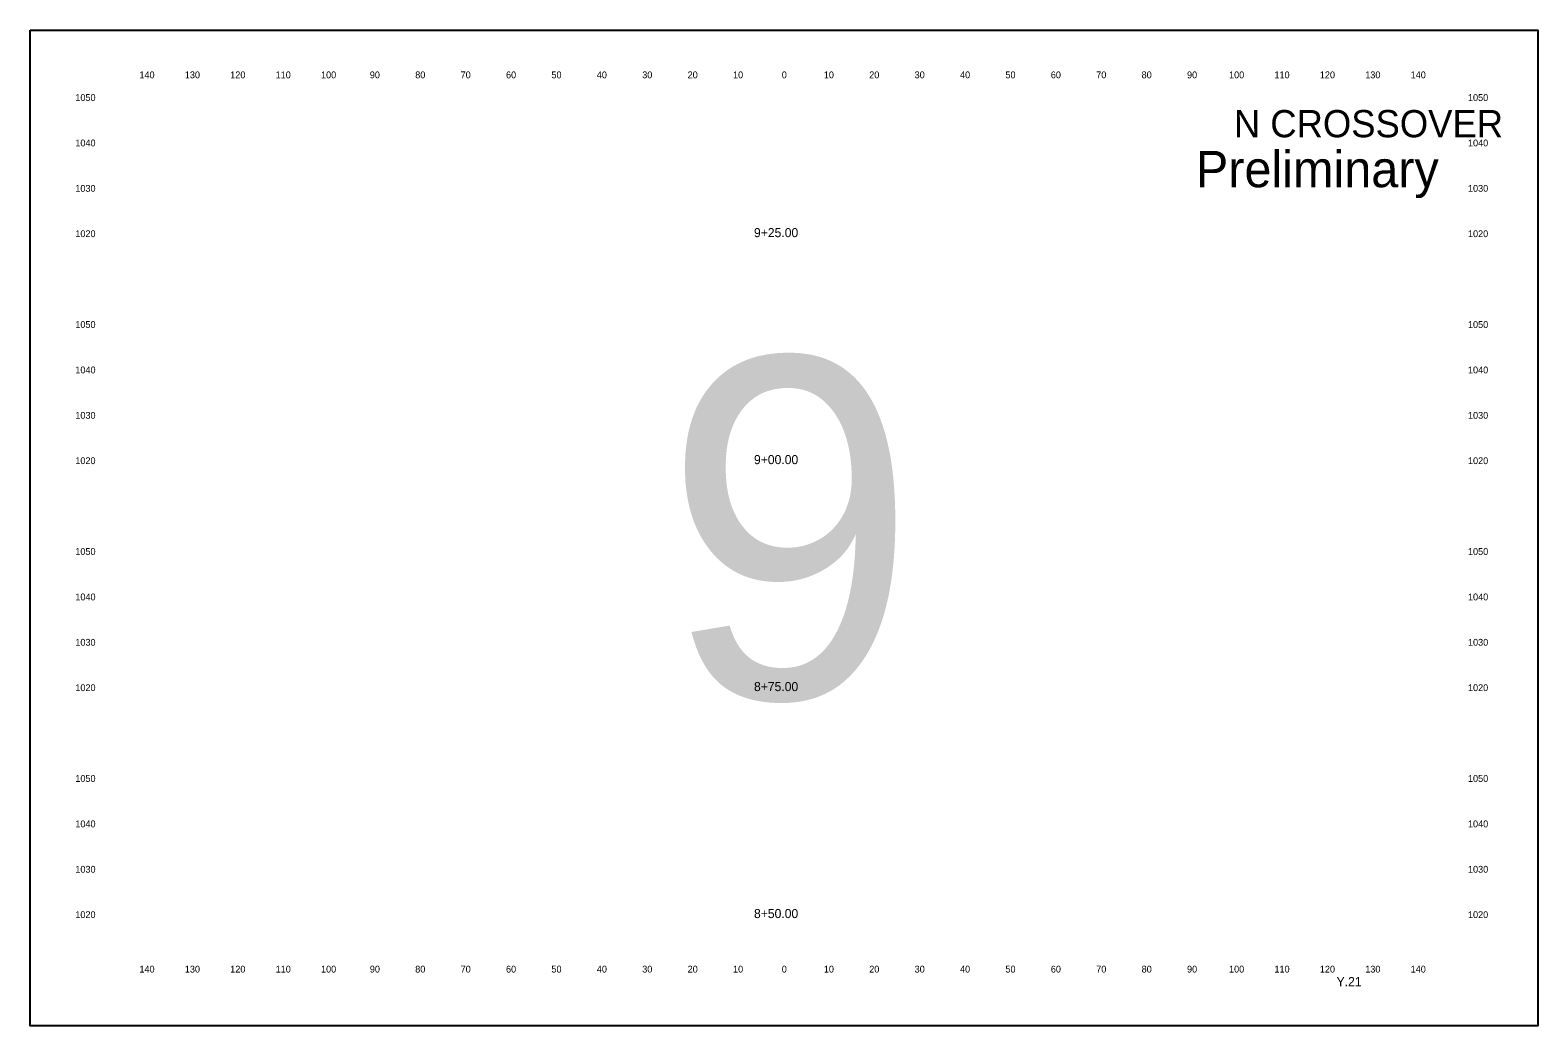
# Model space of a CAD drawing. Extents: x 10123 to 14767, y 9730 to 9950.
# Drawn here: x 13003.2 to 13335.3, y 9730.3 to 9949.6 of the extents above; entities that cross this region are included whole.
import ezdxf

# ---------------------------------------------------------------- set-up
doc = ezdxf.new("R2010")
doc.units = 0
for name, color, linetype in [('dsnTextCpn', 7, 'Continuous'), ('dsnTextCpnTitleSheetLocDesc', 7, 'Continuous'), ('dsnTextCpnTitleSheetPIN', 7, 'Continuous'), ('dsnTextCpnTitleSheetWorkType', 7, 'Continuous')]:
    doc.layers.add(name, color=color, linetype=linetype)

msp = doc.modelspace()

# ---------------------------------------------------------------- linework, layer by layer
at = {"layer": 'dsnTextCpnTitleSheetWorkType'}
msp.add_lwpolyline([(13003.21, 9949.6), (13335.29, 9949.6), (13335.29, 9730.26), (13003.21, 9730.26)], close=True, dxfattribs=at)

# ---------------------------------------------------------------- texts
at = {"layer": 'dsnTextCpn'}
for s, height, p in [('140', 1.5, (13027.27, 9939)), ('130', 1.5, (13037.27, 9939)), ('120', 1.5, (13047.27, 9939)), ('110', 1.5, (13057.27, 9939)), ('100', 1.5, (13067.27, 9939)), ('90', 1.5, (13078.02, 9939)), ('80', 1.5, (13088.02, 9939)), ('70', 1.5, (13098.02, 9939)), ('60', 1.5, (13108.02, 9939)), ('50', 1.5, (13118.02, 9939)), ('40', 1.5, (13128.02, 9939)), ('30', 1.5, (13138.02, 9939)), ('20', 1.5, (13148.02, 9939)), ('10', 1.5, (13158.02, 9939)), ('0', 1.5, (13168.76, 9939)), ('0', 1.5, (13168.76, 9939)), ('10', 1.5, (13178.02, 9939)), ('20', 1.5, (13188.02, 9939)), ('30', 1.5, (13198.02, 9939)), ('40', 1.5, (13208.02, 9939)), ('50', 1.5, (13218.02, 9939)), ('60', 1.5, (13228.02, 9939)), ('70', 1.5, (13238.02, 9939)), ('80', 1.5, (13248.02, 9939)), ('90', 1.5, (13258.02, 9939)), ('100', 1.5, (13267.27, 9939)), ('110', 1.5, (13277.27, 9939)), ('120', 1.5, (13287.27, 9939)), ('130', 1.5, (13297.27, 9939)), ('140', 1.5, (13307.27, 9939)), ('1050', 1.5, (13013.15, 9934)), ('1050', 1.5, (13319.9, 9934)), ('N CROSSOVER', 6, (13268.34, 9926)), ('1040', 1.5, (13013.15, 9924)), ('1040', 1.5, (13319.9, 9924)), ('1030', 1.5, (13013.15, 9914)), ('1030', 1.5, (13319.9, 9914)), ('1020', 1.5, (13013.15, 9904)), ('9+25.00', 2, (13162.64, 9904)), ('1020', 1.5, (13319.9, 9904)), ('1050', 1.5, (13013.15, 9884)), ('1050', 1.5, (13319.9, 9884)), ('1040', 1.5, (13013.15, 9874)), ('1040', 1.5, (13319.9, 9874)), ('1030', 1.5, (13013.15, 9864)), ('1030', 1.5, (13319.9, 9864)), ('1020', 1.5, (13013.15, 9854)), ('9+00.00', 2, (13162.64, 9854)), ('1020', 1.5, (13319.9, 9854)), ('1050', 1.5, (13013.15, 9834)), ('1050', 1.5, (13319.9, 9834)), ('1040', 1.5, (13013.15, 9824)), ('1040', 1.5, (13319.9, 9824)), ('1030', 1.5, (13013.15, 9814)), ('1030', 1.5, (13319.9, 9814)), ('1020', 1.5, (13013.15, 9804)), ('8+75.00', 2, (13162.64, 9804)), ('1020', 1.5, (13319.9, 9804)), ('1050', 1.5, (13013.15, 9784)), ('1050', 1.5, (13319.9, 9784)), ('1040', 1.5, (13013.15, 9774)), ('1040', 1.5, (13319.9, 9774)), ('1030', 1.5, (13013.15, 9764)), ('1030', 1.5, (13319.9, 9764)), ('1020', 1.5, (13013.15, 9754)), ('8+50.00', 2, (13162.64, 9754)), ('1020', 1.5, (13319.9, 9754)), ('140', 1.5, (13027.27, 9742)), ('130', 1.5, (13037.27, 9742)), ('120', 1.5, (13047.27, 9742)), ('110', 1.5, (13057.27, 9742)), ('100', 1.5, (13067.27, 9742)), ('90', 1.5, (13078.02, 9742)), ('80', 1.5, (13088.02, 9742)), ('70', 1.5, (13098.02, 9742)), ('60', 1.5, (13108.02, 9742)), ('50', 1.5, (13118.02, 9742)), ('40', 1.5, (13128.02, 9742)), ('30', 1.5, (13138.02, 9742)), ('20', 1.5, (13148.02, 9742)), ('10', 1.5, (13158.02, 9742)), ('0', 1.5, (13168.76, 9742)), ('0', 1.5, (13168.76, 9742)), ('10', 1.5, (13178.02, 9742)), ('20', 1.5, (13188.02, 9742)), ('30', 1.5, (13198.02, 9742)), ('40', 1.5, (13208.02, 9742)), ('50', 1.5, (13218.02, 9742)), ('60', 1.5, (13228.02, 9742)), ('70', 1.5, (13238.02, 9742)), ('80', 1.5, (13248.02, 9742)), ('90', 1.5, (13258.02, 9742)), ('100', 1.5, (13267.27, 9742)), ('110', 1.5, (13277.27, 9742)), ('120', 1.5, (13287.27, 9742)), ('130', 1.5, (13297.27, 9742)), ('140', 1.5, (13307.27, 9742))]:
    msp.add_text(s, height=height, dxfattribs=at).set_placement(p)
at = {"layer": 'dsnTextCpnTitleSheetLocDesc'}
msp.add_text('Preliminary', height=8, dxfattribs=at).set_placement((13259.97, 9915))
at = {"layer": 'dsnTextCpnTitleSheetPIN'}
msp.add_text('Y.21', height=2, dxfattribs=at).set_placement((13290.96, 9739))
at = {"layer": 'dsnTextCpnTitleSheetWorkType'}
msp.add_text('9', height=75, dxfattribs=at).set_placement((13142.74, 9802.43))

doc.saveas('drawing.dxf')
